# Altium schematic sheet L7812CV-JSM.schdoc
size 127 x 101 mm
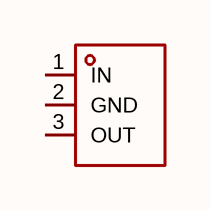
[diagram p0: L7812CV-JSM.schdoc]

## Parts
U?  l7812cv-jsm  [TO-220-3_L10.2-W4.5-P2.54-L-2]  (value not drawn)

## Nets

Not connected (* = marked no-connect by the designer): U? 1(IN) 2(GND) 3(OUT)

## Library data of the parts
U? = l7812cv-jsm: 输出极性:正极;工作电压:35V;输出电压:12V;输出电流:1.5A;电源纹波抑制比(PSRR):55dB@(120Hz);输出类型:固定;; Manufacturer: JSMSEMI(杰盛微); AddInBom: yes; ModelId: 1ca563dca8cf40409ecd70c91a2e4989; ModelTransform: 401.574,177.559,0,0,0,0,0,29.527,-196.85; Output Configuration: 正极; Voltage - Supply: 35V; Output Voltage: 12V; Output Current: 1.5A; Voltage Dropout: 2V@(1A); standby current: 8mA; Noise: 75uV; Output Type: 固定; Number of Outputs: 1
